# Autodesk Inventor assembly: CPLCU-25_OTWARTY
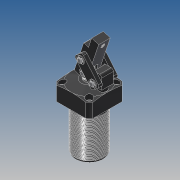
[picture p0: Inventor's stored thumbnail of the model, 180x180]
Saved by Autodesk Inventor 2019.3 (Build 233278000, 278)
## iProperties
Created: 2010-03
Part Number: CPLCU-25_OTWARTY
Material: Ogólny
Document SubType Name: Assembly
Designer: CADENGINEERING4
Sending System: PRO/ENGINEER BY PARAMETRIC TECHNOLOGY CORPORATION, 2007170
Preprocessor: PRO/ENGINEER BY PARAMETRIC TECHNOLOGY CORPORATION, 2007170
Title: CPLCU-25_ASM
Author: Administrator
Revision Number: 1LAST_VERSION
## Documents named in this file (10)
- E:\SERWER_ZAPAS\MODELE brakujace\PNEUMATIC\CPLCU(STEP)\cplcu-25_asm\CPLCU-25_OTWARTY.iam
- E:\SERWER_ZAPAS\MODELE brakujace\PNEUMATIC\CPLCU(STEP)\cplcu-25_asm\CPLCU-25-07.ipt
- E:\SERWER_ZAPAS\MODELE brakujace\PNEUMATIC\CPLCU(STEP)\cplcu-25_asm\CPLCU-25-06.ipt
- E:\SERWER_ZAPAS\MODELE brakujace\PNEUMATIC\CPLCU(STEP)\cplcu-25_asm\CPLCU-25-01.ipt
- E:\SERWER_ZAPAS\MODELE brakujace\PNEUMATIC\CPLCU(STEP)\cplcu-25_asm\CPLCU-25-05.ipt
- E:\SERWER_ZAPAS\MODELE brakujace\PNEUMATIC\CPLCU(STEP)\cplcu-25_asm\CPLCU-25-02.ipt
- E:\SERWER_ZAPAS\MODELE brakujace\PNEUMATIC\CPLCU(STEP)\cplcu-25_asm\CPLCU-25-09.ipt
- E:\SERWER_ZAPAS\MODELE brakujace\PNEUMATIC\CPLCU(STEP)\cplcu-25_asm\CPLCU-25-03.ipt
- E:\SERWER_ZAPAS\MODELE brakujace\PNEUMATIC\CPLCU(STEP)\cplcu-25_asm\CPLCU-25-04.ipt
- E:\SERWER_ZAPAS\MODELE brakujace\PNEUMATIC\CPLCU(STEP)\cplcu-25_asm\LHC01D-32-01.ipt
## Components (21 placed, 21 different names)
1. CPLCU-25-07_0 — Zestawiające:17, Zestawiające:32
2. CPLCU-25-06_1 — Zestawiające:1, Równoległe:1, Zestawiające:4, Zestawiające:5, Zestawiające:7, Zestawiające:17, Zestawiające:32
3. CPLCU-25-01_2 — Zestawiające:6, Zestawiające:7, Zestawiające:10, Zestawiające:11, Zestawiające:12, Zestawiające:16, Zestawiające:20
4. CPLCU-25-05_3 — Zestawiające:25, Zestawiające:26, Zestawiające:28, Zestawiające:29
5. CPLCU-25-02_4 — Zestawiające:12, Zestawiające:13, Równoległe:2, Zestawiające:19, Zestawiające:24
6. CPLCU-25-02_5 — Zestawiające:14, Równoległe:3, Zestawiające:19, Zestawiające:20, Zestawiające:22, Zestawiające:26, Zestawiające:31
7. CPLCU-25-09_6 — Zestawiające:3, Zestawiające:4
8. CPLCU-25-09_7 — Zestawiające:13, Równoległe:2, Zestawiające:18
9. CPLCU-25-09_8 — Zestawiające:29, Zestawiające:30
10. CPLCU-25-09_9 — Zestawiające:27, Zestawiające:28, Zestawiające:31
11. CPLCU-25-09_10 — Zestawiające:14, Równoległe:3, Zestawiające:15
12. CPLCU-25-09_11 — Zestawiające:2, Zestawiające:5, Zestawiające:6
13. CPLCU-25-03_12 — Zestawiające:1, Równoległe:1, Zestawiające:2, Zestawiające:3, Zestawiające:8, Zestawiające:9
14. CPLCU-25-04_13 — Zestawiające:25, Równoległe:4, Zestawiające:27, Zestawiające:30
15. CPLCU-25-04_14 — Zestawiające:15, Zestawiające:16, Zestawiające:18, Zestawiające:21, Zestawiające:23, Równoległe:4, Równoległe:5
16. LHC01D-32-01_15 — Zestawiające:9, Zestawiające:10
17. LHC01D-32-01_16 — Zestawiające:8, Zestawiające:11
18. LHC01D-32-01_17 — Zestawiające:23, Zestawiające:24
19. LHC01D-32-01_18
20. LHC01D-32-01_19 — Zestawiające:21, Zestawiające:22, Równoległe:5
21. LHC01D-32-01_20
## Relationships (37: Mate 32, Flush 5)
- Zestawiające:1 [Mate]: CPLCU-25-06_1 ↔ CPLCU-25-03_12
- Równoległe:1 [Flush]: CPLCU-25-06_1 ↔ CPLCU-25-03_12
- Zestawiające:2 [Mate]: CPLCU-25-09_11 ↔ CPLCU-25-03_12
- Zestawiające:3 [Mate]: CPLCU-25-09_6 ↔ CPLCU-25-03_12
- Zestawiające:4 [Mate]: CPLCU-25-06_1 ↔ CPLCU-25-09_6
- Zestawiające:5 [Mate]: CPLCU-25-06_1 ↔ CPLCU-25-09_11
- Zestawiające:6 [Mate]: CPLCU-25-01_2 ↔ CPLCU-25-09_11
- Zestawiające:7 [Mate]: CPLCU-25-06_1 ↔ CPLCU-25-01_2
- Zestawiające:8 [Mate]: CPLCU-25-03_12 ↔ LHC01D-32-01_16
- Zestawiające:9 [Mate]: CPLCU-25-03_12 ↔ LHC01D-32-01_15
- Zestawiające:10 [Mate]: CPLCU-25-01_2 ↔ LHC01D-32-01_15
- Zestawiające:11 [Mate]: CPLCU-25-01_2 ↔ LHC01D-32-01_16
- Zestawiające:12 [Mate]: CPLCU-25-01_2 ↔ CPLCU-25-02_4
- Zestawiające:13 [Mate]: CPLCU-25-02_4 ↔ CPLCU-25-09_7
- Równoległe:2 [Flush]: CPLCU-25-02_4 ↔ CPLCU-25-09_7
- Zestawiające:14 [Mate]: CPLCU-25-02_5 ↔ CPLCU-25-09_10
- Równoległe:3 [Flush]: CPLCU-25-02_5 ↔ CPLCU-25-09_10
- Zestawiające:15 [Mate]: CPLCU-25-09_10 ↔ CPLCU-25-04_14
- Zestawiające:16 [Mate]: CPLCU-25-01_2 ↔ CPLCU-25-04_14
- Zestawiające:17 [Mate]: CPLCU-25-07_0 ↔ CPLCU-25-06_1
- Zestawiające:18 [Mate]: CPLCU-25-09_7 ↔ CPLCU-25-04_14
- Zestawiające:19 [Mate]: CPLCU-25-02_4 ↔ CPLCU-25-02_5
- Zestawiające:20 [Mate]: CPLCU-25-01_2 ↔ CPLCU-25-02_5
- Zestawiające:21 [Mate]: CPLCU-25-04_14 ↔ LHC01D-32-01_19
- Zestawiające:22 [Mate]: CPLCU-25-02_5 ↔ LHC01D-32-01_19
- Zestawiające:23 [Mate]: CPLCU-25-04_14 ↔ LHC01D-32-01_17
- Zestawiające:24 [Mate]: CPLCU-25-02_4 ↔ LHC01D-32-01_17
- Zestawiające:25 [Mate]: CPLCU-25-05_3 ↔ CPLCU-25-04_13
- Równoległe:4 [Flush]: CPLCU-25-04_13 ↔ CPLCU-25-04_14
- Zestawiające:26 [Mate]: CPLCU-25-05_3 ↔ CPLCU-25-02_5
- Zestawiające:27 [Mate]: CPLCU-25-09_9 ↔ CPLCU-25-04_13
- Zestawiające:28 [Mate]: CPLCU-25-05_3 ↔ CPLCU-25-09_9
- Zestawiające:29 [Mate]: CPLCU-25-05_3 ↔ CPLCU-25-09_8
- Zestawiające:30 [Mate]: CPLCU-25-09_8 ↔ CPLCU-25-04_13
- Zestawiające:31 [Mate]: CPLCU-25-02_5 ↔ CPLCU-25-09_9
- Równoległe:5 [Flush]: CPLCU-25-04_14 ↔ LHC01D-32-01_19
- Zestawiające:32 [Mate]: CPLCU-25-07_0 ↔ CPLCU-25-06_1
